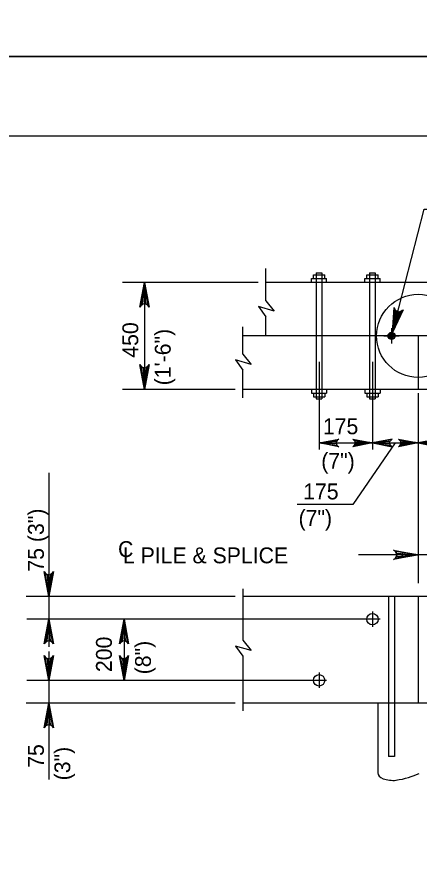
# Model space of a CAD drawing. Extents: x 635440 to 640306, y 296653 to 298484.
# Drawn here: x 638990 to 639066.1, y 297095.9 to 297255 of the extents above; entities that cross this region are included whole.
import ezdxf

# ---------------------------------------------------------------- set-up
doc = ezdxf.new("R2010")
doc.units = 0
for name, color, linetype in [('2', 7, 'Continuous'), ('4', 7, 'Continuous'), ('5', 7, 'Continuous'), ('52', 7, 'Continuous'), ('PLT-BNDY', 7, 'Continuous')]:
    doc.layers.add(name, color=color, linetype=linetype)

msp = doc.modelspace()

# ---------------------------------------------------------------- linework, layer by layer
at = {"layer": '2'}
msp.add_line((638475.46, 297232.46), (639261.46, 297232.46), dxfattribs=at)
at = {"layer": '4'}
for p, q in [((639037.07, 297201.36), (639037.07, 297207.46)), ((639046.05, 297205.53), (639046.05, 297206.25)), ((639046.05, 297206.25), (639048.21, 297206.25)), ((639046.59, 297206.61), (639047.67, 297206.61)), ((639046.59, 297206.61), (639046.59, 297182.82)), ((639047.67, 297206.61), (639047.67, 297182.82)), ((639048.21, 297205.53), (639048.21, 297206.25)), ((639056.14, 297205.53), (639056.14, 297206.25)), ((639056.14, 297206.25), (639058.3, 297206.25)), ((639056.68, 297206.61), (639057.76, 297206.61)), ((639056.68, 297206.61), (639056.68, 297182.82)), ((639057.76, 297206.61), (639057.76, 297182.82)), ((639058.3, 297205.53), (639058.3, 297206.25)), ((639192.72, 297204.81), (639037.07, 297204.81)), ((639045.69, 297204.81), (639045.69, 297205.53)), ((639045.69, 297205.53), (639048.57, 297205.53)), ((639048.57, 297204.81), (639048.57, 297205.53)), ((639055.78, 297204.81), (639055.78, 297205.53)), ((639055.78, 297205.53), (639058.66, 297205.53)), ((639058.66, 297204.81), (639058.66, 297205.53)), ((639037.07, 297201.36), (639038.66, 297199.41)), ((639038.66, 297199.41), (639035.68, 297200.26)), ((639035.68, 297200.26), (639037.07, 297198.34)), ((639037.07, 297194.71), (639037.07, 297198.34)), ((639032.71, 297191.27), (639032.71, 297196.4)), ((639060.83, 297196.15), (639060.83, 297193.27)), ((639197.08, 297194.71), (639032.71, 297194.71)), ((639059.39, 297194.71), (639062.27, 297194.71)), ((639065.87, 297194.71), (639065.87, 297184.62)), ((639032.71, 297191.27), (639034.3, 297189.32)), ((639031.32, 297190.16), (639032.71, 297188.25)), ((639034.3, 297189.32), (639031.32, 297190.16)), ((639032.71, 297183.04), (639032.71, 297188.25)), ((639197.08, 297184.62), (639032.71, 297184.62)), ((639045.69, 297184.62), (639045.69, 297183.9)), ((639045.69, 297183.9), (639048.57, 297183.9)), ((639046.05, 297183.9), (639046.05, 297183.18)), ((639048.21, 297183.9), (639048.21, 297183.18)), ((639048.57, 297184.62), (639048.57, 297183.9)), ((639055.78, 297184.62), (639055.78, 297183.9)), ((639055.78, 297183.9), (639058.66, 297183.9)), ((639056.14, 297183.9), (639056.14, 297183.18)), ((639058.3, 297183.9), (639058.3, 297183.18)), ((639058.66, 297184.62), (639058.66, 297183.9)), ((639046.05, 297183.18), (639048.21, 297183.18)), ((639046.59, 297182.82), (639047.67, 297182.82)), ((639056.14, 297183.18), (639058.3, 297183.18)), ((639056.68, 297182.82), (639057.76, 297182.82)), ((639032.71, 297146.98), (639032.71, 297137.25)), ((639197.08, 297145.53), (639032.71, 297145.53)), ((639060.29, 297145.53), (639060.29, 297115.26)), ((639061.37, 297145.53), (639061.37, 297115.26)), ((639065.87, 297145.53), (639065.87, 297125.35)), ((639057.22, 297142.65), (639057.22, 297139.77)), ((639032.71, 297137.25), (639034.3, 297135.3)), ((639031.32, 297136.15), (639032.71, 297134.23)), ((639034.3, 297135.3), (639031.32, 297136.15)), ((639032.71, 297134.23), (639032.71, 297123.91)), ((639047.13, 297131.12), (639047.13, 297128.23)), ((639197.08, 297125.35), (639032.71, 297125.35)), ((639058.22, 297125.35), (639058.22, 297112.21)), ((639061.37, 297115.26), (639060.29, 297115.26))]:
    msp.add_line(p, q, dxfattribs=at)
for centre, radius in [((639065.87, 297194.71), 7.85), ((639057.22, 297141.21), 1.08), ((639047.13, 297129.68), 1.08)]:
    msp.add_circle(centre, radius, dxfattribs=at)
for centre, major_axis, start_param, end_param in [((639061, 297112.17), (-2.78, 0.05), 0, 1.827597), ((639058.28, 297116.14), (-11.09, 0.18), 1.89032, 2.356194)]:
    msp.add_ellipse(centre, major_axis=major_axis, ratio=0.5, start_param=start_param, end_param=end_param, dxfattribs=at)
at = {"layer": '5'}
for p, q in [((639035.63, 297204.81), (639009.98, 297204.81)), ((639014.13, 297204.81), (639014.13, 297184.62)), ((639047.13, 297189.79), (639047.13, 297173.25)), ((639057.22, 297189.79), (639057.22, 297173.25)), ((639031.27, 297184.62), (639009.98, 297184.62)), ((639065.87, 297183.9), (639065.87, 297147.99)), ((639047.13, 297174.49), (639114.9, 297174.49)), ((638996.04, 297168.87), (638996.04, 297141.21)), ((639163.92, 297153.37), (639054.58, 297153.37)), ((639031.27, 297145.53), (638991.79, 297145.53)), ((639058.66, 297141.21), (638991.87, 297141.21)), ((639010.26, 297141.21), (639010.26, 297129.67)), ((638996.04, 297140.17), (638996.04, 297136.01)), ((638996.04, 297135.09), (638996.04, 297134.7)), ((638996.04, 297134.87), (638996.04, 297125.35)), ((639048.57, 297129.67), (638991.87, 297129.67)), ((638996.04, 297129.67), (638996.04, 297110.92)), ((639031.27, 297125.35), (638991.79, 297125.35))]:
    msp.add_line(p, q, dxfattribs=at)
for points in [[(639060.99, 297195.36), (639067.03, 297218.62), (639082.43, 297218.62)], [(639014.13, 297204.81), (639015, 297200.15), (639014.75, 297200.5), (639014.44, 297200.69), (639014.13, 297200.74), (639013.82, 297200.69), (639013.5, 297200.5), (639013.26, 297200.15), (639014.13, 297204.81), (639013.5, 297200.5), (639013.82, 297200.69), (639014.13, 297204.81), (639014.13, 297200.74), (639014.44, 297200.69), (639014.13, 297204.81), (639014.75, 297200.5)], [(639060.99, 297195.36), (639061.32, 297200.09), (639061.39, 297199.88), (639061.47, 297199.68), (639061.6, 297199.55), (639061.72, 297199.42), (639061.87, 297199.36), (639062.01, 297199.29), (639062.17, 297199.28), (639062.33, 297199.27), (639062.5, 297199.32), (639062.68, 297199.37), (639062.84, 297199.51), (639063.01, 297199.65), (639060.99, 297195.36), (639062.84, 297199.51), (639062.68, 297199.37), (639060.99, 297195.36), (639062.5, 297199.32), (639062.33, 297199.27), (639060.99, 297195.36), (639062.17, 297199.28), (639062.01, 297199.29), (639060.99, 297195.36), (639061.87, 297199.36), (639061.72, 297199.42), (639060.99, 297195.36), (639061.6, 297199.55), (639061.47, 297199.68), (639060.99, 297195.36), (639061.39, 297199.88)], [(639014.13, 297184.62), (639013.26, 297189.28), (639013.5, 297188.92), (639013.82, 297188.74), (639014.13, 297188.68), (639014.44, 297188.74), (639014.75, 297188.92), (639015, 297189.28), (639014.13, 297184.62), (639014.75, 297188.92), (639014.44, 297188.74), (639014.13, 297184.62), (639014.13, 297188.68), (639013.82, 297188.74), (639014.13, 297184.62), (639013.5, 297188.92)], [(639047.13, 297174.49), (639050.86, 297175.19), (639050.57, 297174.99), (639050.42, 297174.74), (639050.38, 297174.49), (639050.42, 297174.24), (639050.57, 297173.99), (639050.86, 297173.79), (639047.13, 297174.49), (639050.57, 297173.99), (639050.42, 297174.24), (639047.13, 297174.49), (639050.38, 297174.49), (639050.42, 297174.74), (639047.13, 297174.49), (639050.57, 297174.99)], [(639057.22, 297174.49), (639053.49, 297173.79), (639053.78, 297173.99), (639053.93, 297174.24), (639053.97, 297174.49), (639053.93, 297174.74), (639053.78, 297174.99), (639053.49, 297175.19), (639057.22, 297174.49), (639053.78, 297174.99), (639053.93, 297174.74), (639057.22, 297174.49), (639053.97, 297174.49), (639053.93, 297174.24), (639057.22, 297174.49), (639053.78, 297173.99)], [(639057.22, 297174.49), (639060.95, 297173.79), (639060.67, 297173.99), (639060.52, 297174.24), (639060.47, 297174.49), (639060.52, 297174.74), (639060.67, 297174.99), (639060.95, 297175.19), (639057.22, 297174.49), (639060.67, 297174.99), (639060.52, 297174.74), (639057.22, 297174.49), (639060.47, 297174.49), (639060.52, 297174.24), (639057.22, 297174.49), (639060.67, 297173.99)], [(639065.87, 297174.49), (639062.14, 297173.79), (639062.43, 297173.99), (639062.58, 297174.24), (639062.62, 297174.49), (639062.58, 297174.74), (639062.43, 297174.99), (639062.14, 297175.19), (639065.87, 297174.49), (639062.43, 297174.99), (639062.58, 297174.74), (639065.87, 297174.49), (639062.62, 297174.49), (639062.58, 297174.24), (639065.87, 297174.49), (639062.43, 297173.99)], [(639065.87, 297174.49), (639069.6, 297173.79), (639069.32, 297173.99), (639069.17, 297174.24), (639069.12, 297174.49), (639069.17, 297174.74), (639069.32, 297174.99), (639069.6, 297175.19), (639065.87, 297174.49), (639069.32, 297174.99), (639069.17, 297174.74), (639065.87, 297174.49), (639069.12, 297174.49), (639069.17, 297174.24), (639065.87, 297174.49), (639069.32, 297173.99)], [(639065.87, 297153.37), (639061.21, 297152.5), (639061.57, 297152.74), (639061.76, 297153.06), (639061.81, 297153.37), (639061.76, 297153.68), (639061.57, 297153.99), (639061.21, 297154.24), (639065.87, 297153.37), (639061.57, 297153.99), (639061.76, 297153.68), (639065.87, 297153.37), (639061.81, 297153.37), (639061.76, 297153.06), (639065.87, 297153.37), (639061.57, 297152.74)], [(638996.04, 297145.53), (638995.16, 297150.2), (638995.41, 297149.84), (638995.72, 297149.65), (638996.04, 297149.6), (638996.35, 297149.65), (638996.66, 297149.84), (638996.91, 297150.2), (638996.04, 297145.53), (638996.66, 297149.84), (638996.35, 297149.65), (638996.04, 297145.53), (638996.04, 297149.6), (638995.72, 297149.65), (638996.04, 297145.53), (638995.41, 297149.84)], [(638996.04, 297141.21), (638996.91, 297136.55), (638996.66, 297136.91), (638996.35, 297137.09), (638996.04, 297137.15), (638995.72, 297137.09), (638995.41, 297136.91), (638995.16, 297136.55), (638996.04, 297141.21), (638995.41, 297136.91), (638995.72, 297137.09), (638996.04, 297141.21), (638996.04, 297137.15), (638996.35, 297137.09), (638996.04, 297141.21), (638996.66, 297136.91)], [(639010.26, 297141.21), (639011.13, 297136.55), (639010.88, 297136.91), (639010.57, 297137.09), (639010.26, 297137.15), (639009.95, 297137.09), (639009.63, 297136.91), (639009.39, 297136.55), (639010.26, 297141.21), (639009.63, 297136.91), (639009.95, 297137.09), (639010.26, 297141.21), (639010.26, 297137.15), (639010.57, 297137.09), (639010.26, 297141.21), (639010.88, 297136.91)], [(638996.04, 297129.67), (638995.16, 297134.33), (638995.41, 297133.98), (638995.72, 297133.79), (638996.04, 297133.74), (638996.35, 297133.79), (638996.66, 297133.98), (638996.91, 297134.33), (638996.04, 297129.67), (638996.66, 297133.98), (638996.35, 297133.79), (638996.04, 297129.67), (638996.04, 297133.74), (638995.72, 297133.79), (638996.04, 297129.67), (638995.41, 297133.98)], [(639010.26, 297129.67), (639009.39, 297134.33), (639009.63, 297133.98), (639009.95, 297133.79), (639010.26, 297133.74), (639010.57, 297133.79), (639010.88, 297133.98), (639011.13, 297134.33), (639010.26, 297129.67), (639010.88, 297133.98), (639010.57, 297133.79), (639010.26, 297129.67), (639010.26, 297133.74), (639009.95, 297133.79), (639010.26, 297129.67), (639009.63, 297133.98)], [(638996.04, 297125.35), (638996.91, 297120.69), (638996.66, 297121.05), (638996.35, 297121.23), (638996.04, 297121.29), (638995.72, 297121.23), (638995.41, 297121.05), (638995.16, 297120.69), (638996.04, 297125.35), (638995.41, 297121.05), (638995.72, 297121.23), (638996.04, 297125.35), (638996.04, 297121.29), (638996.35, 297121.23), (638996.04, 297125.35), (638996.66, 297121.05)]]:
    msp.add_lwpolyline(points, dxfattribs=at)
for points in [[(639013.67, 297202.04), (639014.59, 297202.04), (639014.13, 297204.81)], [(639013.67, 297187.39), (639014.59, 297187.39), (639014.13, 297184.62)], [(639062.87, 297153.85), (639062.87, 297152.89), (639065.75, 297153.37)]]:
    msp.add_lwpolyline(points, close=True, dxfattribs=at)
for radius in [0.667, 0.5, 0.333, 0.167]:
    msp.add_circle((639060.83, 297194.71), radius, dxfattribs=at)
at = {"layer": '52'}
msp.add_lwpolyline([(639061.54, 297174.49), (639053.5, 297162.88), (639043, 297162.88)], dxfattribs=at)
at = {"layer": 'PLT-BNDY'}
for points in [[(638435.46, 297841.46), (639276.46, 297841.46), (639276.46, 297247.46), (638435.46, 297247.46)], [(638435.46, 297247.46), (639276.46, 297247.46), (639276.46, 296653.46), (638435.46, 296653.46)]]:
    msp.add_lwpolyline(points, close=True, dxfattribs=at)

# ---------------------------------------------------------------- texts
at = {"layer": '5'}
for s, p in [('450', (639012.95, 297190.59)), ('(1\'-6")', (639019.08, 297185.38)), ('75 (3")', (638995.11, 297150.2)), ('200', (639007.96, 297131.23)), ('(8")', (639015.35, 297130.81)), ('75', (638995.1, 297113.15)), ('(3")', (639000.1, 297110.79))]:
    msp.add_text(s, height=3, rotation=90, dxfattribs=at).set_placement(p)
for s, height, p in [('175', 3, (639047.86, 297176.14)), ('(7")', 3, (639047.55, 297169.62)), ('175', 3, (639044.13, 297163.84)), ('(7")', 3, (639043.26, 297158.84)), ('C', 3, (639009.13, 297152.95)), ('L PILE & SPLICE', 3.0001, (639010.06, 297151.77))]:
    msp.add_text(s, height=height, dxfattribs=at).set_placement(p)

doc.saveas('drawing.dxf')
